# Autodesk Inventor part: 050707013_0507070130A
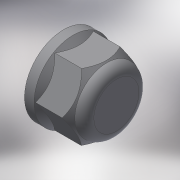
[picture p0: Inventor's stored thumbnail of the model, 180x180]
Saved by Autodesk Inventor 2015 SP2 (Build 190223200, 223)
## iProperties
Created: 2017-05
Part Number: 050707013_0507070130A
Material: Generic
Description: PLASSON CAP 1.1/4"
Document SubType Name: Modeling
Designer: KIM
Density: 1 g/cm^3
Appearance: Default
Author: KIM
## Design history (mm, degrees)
derived "050707.ipt"
feature "Solid1::050707.ipt"
tag "TaggingFeature1"
body "Solid1"
other parameters: "d0" = 34, "d1" = 2.2, "d2" = 38.952, "d3" = 22, "d4" = 2.2, "d5" = 135 deg, "d6" = 42.8472, "d7" = 59, "d8" = 50.15, "d9" = 48.38, "d10" = 135 deg, "d11" = 6.6, "d13" = 6.6, "d16" = 0, "Rp_" = 38.952, "E_" = 59, "H_" = 34, "l_2" = 22
